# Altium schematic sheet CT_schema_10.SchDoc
size 742 x 377 mm
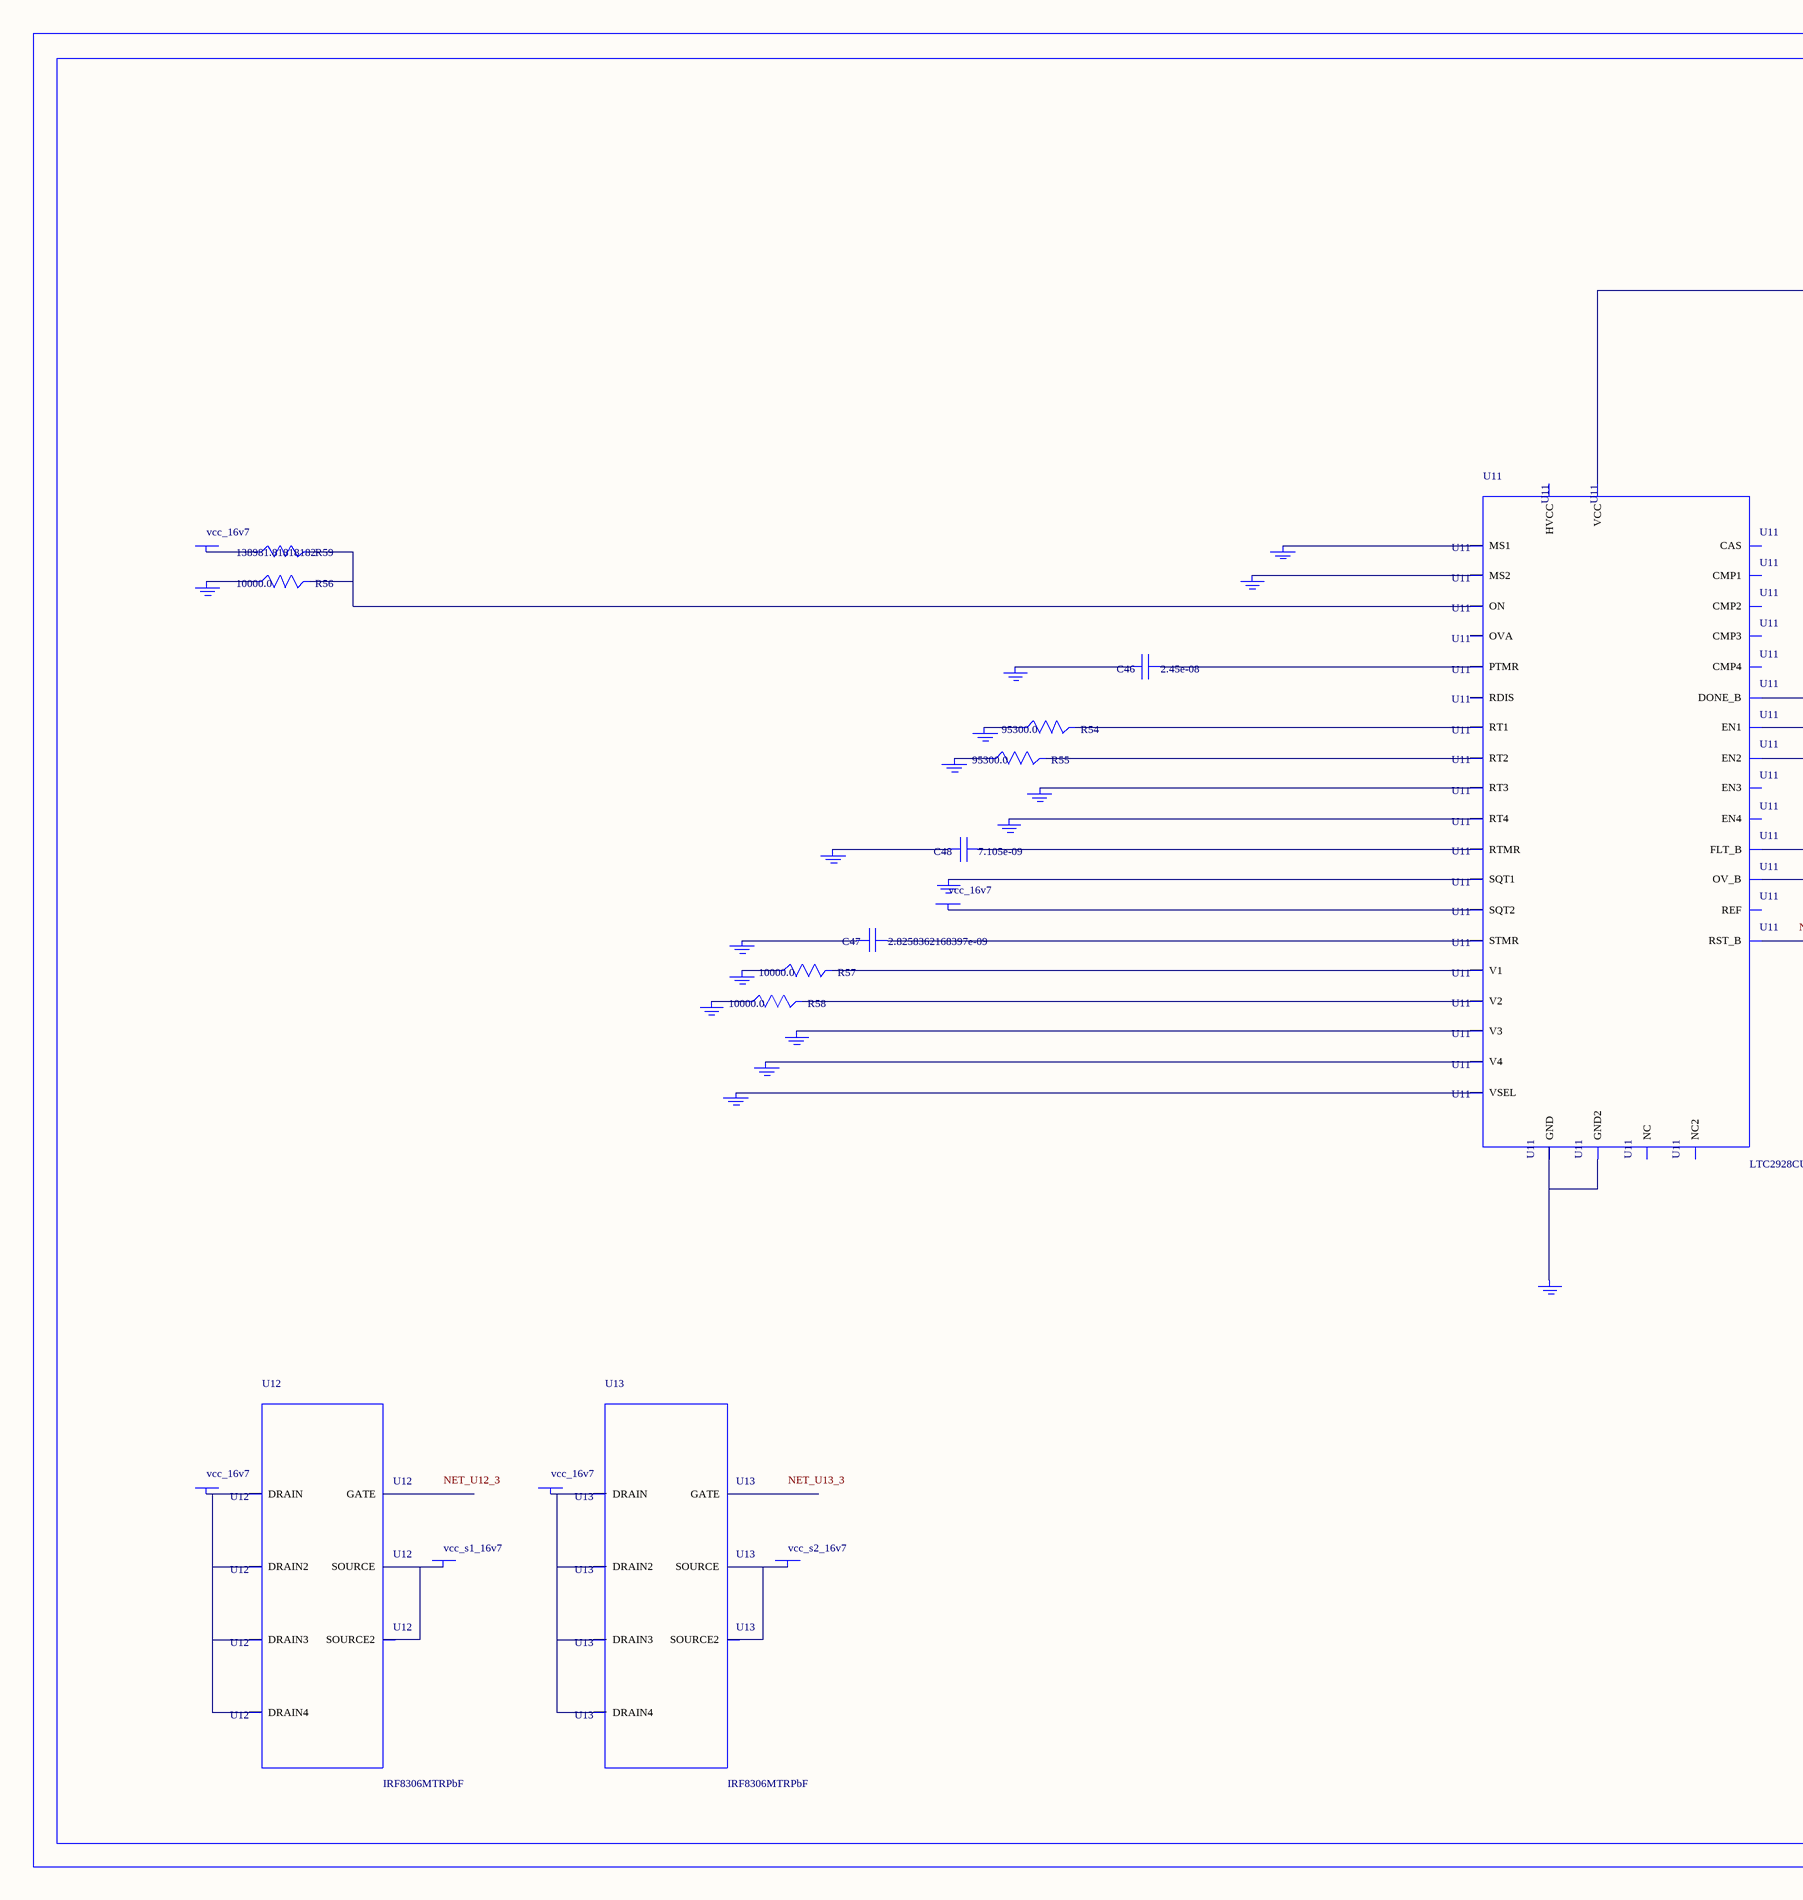
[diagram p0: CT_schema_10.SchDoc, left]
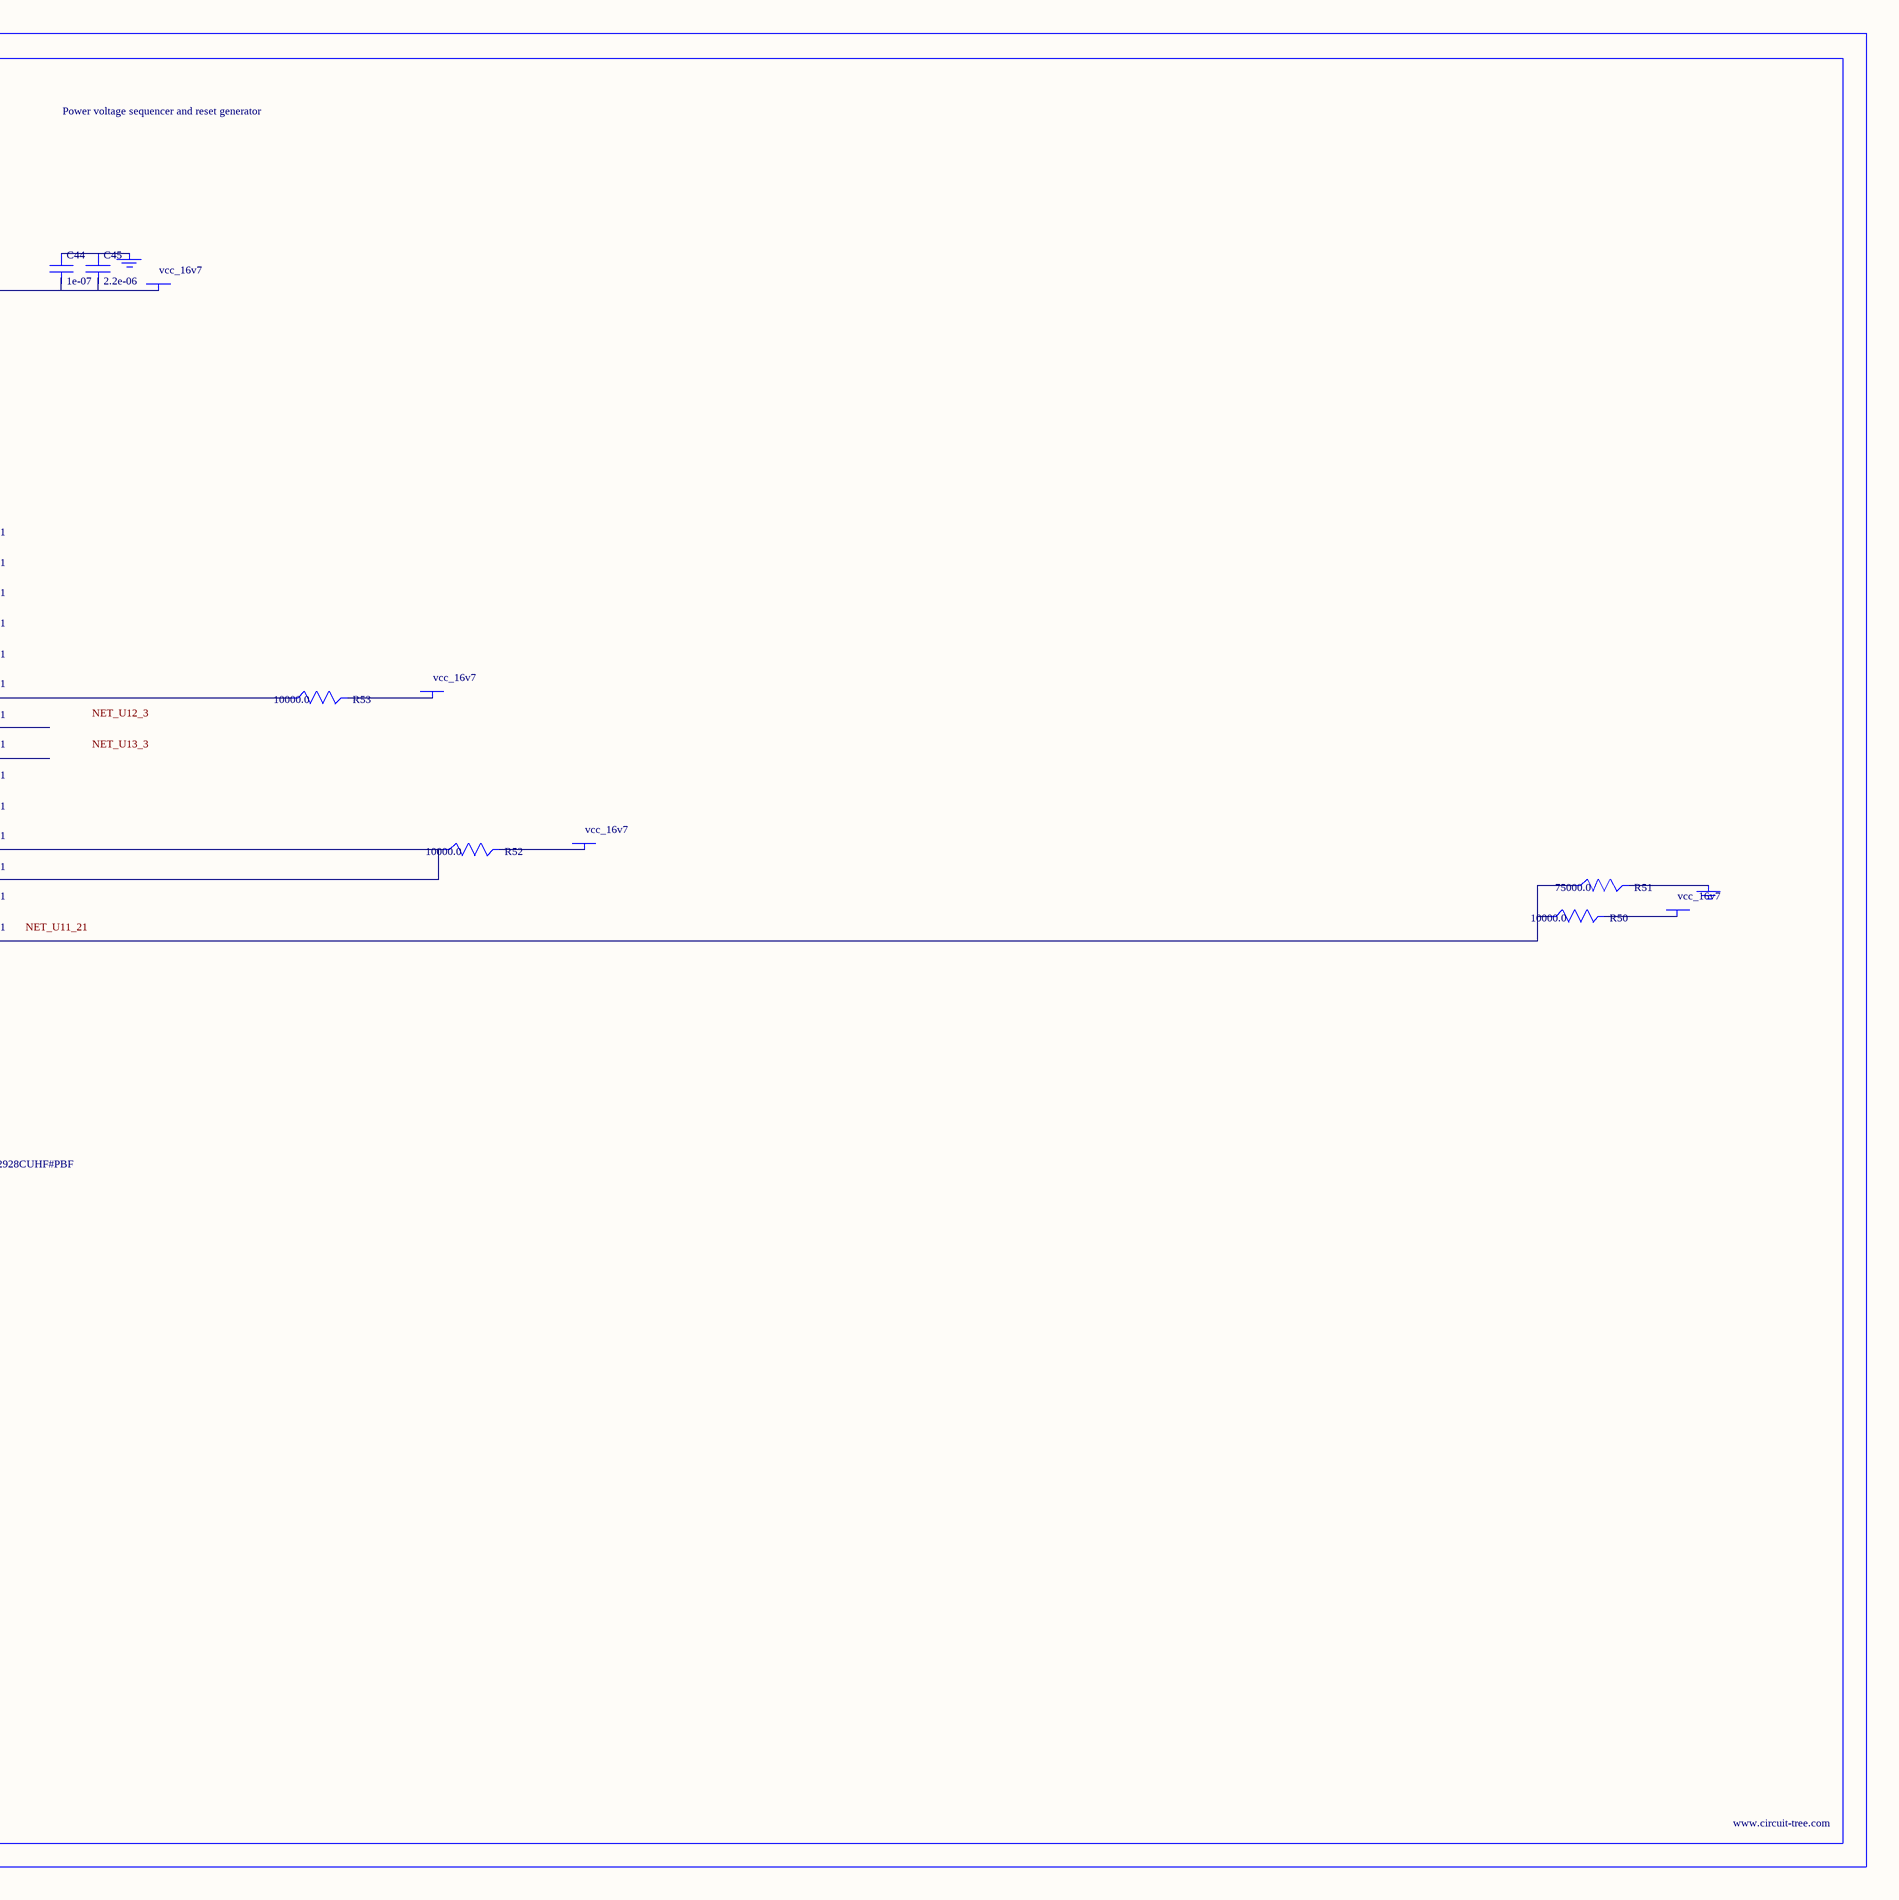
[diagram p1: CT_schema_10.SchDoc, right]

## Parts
BORDER9  (no value)
C44  1e-07  [C0402]
C45  2.2e-06  [C0603]
C46  2.45e-08  [R0603]
C47  2.8258362168397e-09  [R0603]
C48  7.105e-09  [R0603]
GND_INSTANCE_9_0  (no value)
GND_INSTANCE_9_1  (no value)
GND_INSTANCE_9_2  (no value)
GND_INSTANCE_9_3  (no value)
GND_INSTANCE_9_4  (no value)
GND_INSTANCE_9_5  (no value)
GND_INSTANCE_9_6  (no value)
GND_INSTANCE_9_7  (no value)
GND_INSTANCE_9_8  (no value)
GND_INSTANCE_9_9  (no value)
GND_INSTANCE_9_10  (no value)
GND_INSTANCE_9_11  (no value)
GND_INSTANCE_9_12  (no value)
GND_INSTANCE_9_13  (no value)
GND_INSTANCE_9_14  (no value)
GND_INSTANCE_9_15  (no value)
GND_INSTANCE_9_16  (no value)
GND_INSTANCE_9_17  (no value)
GND_INSTANCE_9_18  (no value)
POWER_INSTANCE_9_0  vcc_16v7
POWER_INSTANCE_9_1  vcc_16v7
POWER_INSTANCE_9_2  vcc_16v7
POWER_INSTANCE_9_3  vcc_16v7
POWER_INSTANCE_9_4  vcc_16v7
POWER_INSTANCE_9_5  vcc_16v7
POWER_INSTANCE_9_6  vcc_16v7
POWER_INSTANCE_9_7  vcc_s1_16v7
POWER_INSTANCE_9_8  vcc_16v7
POWER_INSTANCE_9_9  vcc_s2_16v7
R50  10000.0  [R0603]
R51  75000.0  [R0603]
R52  10000.0  [R0603]
R53  10000.0  [R0603]
R54  95300.0  [R0603]
R55  95300.0  [R0603]
R56  10000.0  [R0603]
R57  10000.0  [R0603]
R58  10000.0  [R0603]
R59  138981.81818182  [R0603]
U11  LTC2928CUHF#PBF  [QFN-38_UHF]
U12  IRF8306MTRPbF  [IRF8306MTRPBF]
U13  IRF8306MTRPbF  [IRF8306MTRPBF]

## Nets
NetC44_1: C44.1 C45.1 GND_INSTANCE_9_10.0(GND)
NetC44_2: C44.2 C45.2 POWER_INSTANCE_9_5.0(PWR) U11.22(VCC)
NetC46_1: C46.1 U11.27(PTMR)
NetC46_2: C46.2 GND_INSTANCE_9_13.0(GND)
NetC47_1: C47.1 U11.26(STMR)
NetC47_2: C47.2 GND_INSTANCE_9_12.0(GND)
NetC48_1: C48.1 U11.28(RTMR)
NetC48_2: C48.2 GND_INSTANCE_9_14.0(GND)
NetGND_INSTANCE_9_0_0: GND_INSTANCE_9_0.0(GND) R57.1
NetGND_INSTANCE_9_1_0: GND_INSTANCE_9_1.0(GND) R54.1
NetGND_INSTANCE_9_2_0: GND_INSTANCE_9_2.0(GND) R55.1
NetGND_INSTANCE_9_3_0: GND_INSTANCE_9_3.0(GND) U11.8(RT3)
NetGND_INSTANCE_9_4_0: GND_INSTANCE_9_4.0(GND) U11.9(RT4)
NetGND_INSTANCE_9_5_0: GND_INSTANCE_9_5.0(GND) U11.10(SQT1)
NetGND_INSTANCE_9_6_0: GND_INSTANCE_9_6.0(GND) U11.12(MS1)
NetGND_INSTANCE_9_7_0: GND_INSTANCE_9_7.0(GND) U11.13(MS2)
NetGND_INSTANCE_9_8_0: GND_INSTANCE_9_8.0(GND) R56.1
NetGND_INSTANCE_9_9_0: GND_INSTANCE_9_9.0(GND) R51.2
NetGND_INSTANCE_9_11_0: GND_INSTANCE_9_11.0(GND) U11.25(VSEL)
NetGND_INSTANCE_9_15_0: GND_INSTANCE_9_15.0(GND) U11.30(V4)
NetGND_INSTANCE_9_16_0: GND_INSTANCE_9_16.0(GND) U11.32(V3)
NetGND_INSTANCE_9_17_0: GND_INSTANCE_9_17.0(GND) R58.1
NetGND_INSTANCE_9_18_0: GND_INSTANCE_9_18.0(GND) U11.24(GND) U11.39(GND2)
NetPOWER_INSTANCE_9_0_0: POWER_INSTANCE_9_0.0(PWR) U11.11(SQT2)
NetPOWER_INSTANCE_9_1_0: POWER_INSTANCE_9_1.0(PWR) R59.1
NetPOWER_INSTANCE_9_2_0: POWER_INSTANCE_9_2.0(PWR) R53.2
NetPOWER_INSTANCE_9_3_0: POWER_INSTANCE_9_3.0(PWR) R52.2
NetPOWER_INSTANCE_9_4_0: POWER_INSTANCE_9_4.0(PWR) R50.2
NetPOWER_INSTANCE_9_6_0: POWER_INSTANCE_9_6.0(PWR) U12.1(DRAIN) U12.2(DRAIN2) U12.6(DRAIN3) U12.7(DRAIN4)
NetPOWER_INSTANCE_9_7_0: POWER_INSTANCE_9_7.0(PWR) U12.4(SOURCE) U12.5(SOURCE2)
NetPOWER_INSTANCE_9_8_0: POWER_INSTANCE_9_8.0(PWR) U13.1(DRAIN) U13.2(DRAIN2) U13.6(DRAIN3) U13.7(DRAIN4)
NetPOWER_INSTANCE_9_9_0: POWER_INSTANCE_9_9.0(PWR) U13.4(SOURCE) U13.5(SOURCE2)
NetR50_1: R50.1 R51.1 U11.21(RST_B)
NetR52_1: R52.1 U11.19(FLT_B) U11.20(OV_B)
NetR53_1: R53.1 U11.18(DONE_B)
NetR54_2: R54.2 U11.6(RT1)
NetR55_2: R55.2 U11.7(RT2)
NetR56_2: R56.2 R59.2 U11.16(ON)
NetR57_2: R57.2 U11.3(V1)
NetR58_2: R58.2 U11.38(V2)

Not connected (* = marked no-connect by the designer): U11 1(OVA) 2(EN1) 4(NC) 5(REF) 14(RDIS) 15(CAS) 17(NC2) 23(HVCC) 29(EN4) 31(EN3) 33(CMP3) 34(CMP4) 35(CMP1) 36(CMP2) 37(EN2); U12 3(GATE); U13 3(GATE)

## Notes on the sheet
- Labels drawn without touching a wire or pin: NET_U11_21, NET_U12_3, NET_U13_3

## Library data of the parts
BORDER9 = BORDER_PAGE9
C44 = C0402C104K3RACTU
C45 = GRM188R61H225KE1115D
C46 = C46
C47 = C47
C48 = C48
GND_INSTANCE_9_0-GND_INSTANCE_9_18 = GND
POWER_INSTANCE_9_0-POWER_INSTANCE_9_9 = PWR
R50 R52 R53 R56-R58 = RC0603JR-0710KL
R51 = RC0603JR-0775KL
R54 R55 = RC0603FR-0795K3L
R59 = R59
